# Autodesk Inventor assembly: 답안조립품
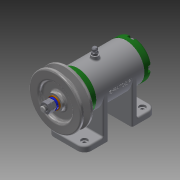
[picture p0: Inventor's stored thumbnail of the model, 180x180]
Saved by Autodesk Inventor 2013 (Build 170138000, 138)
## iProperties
Created: 2017-02
Part Number: 답안조립품
Document SubType Name: Assembly
Designer: Administrator
Author: Administrator
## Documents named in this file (16)
- C:\Users\Administrator\Desktop\470207V1029\답안조립품.iam
- C:\Users\Administrator\Desktop\470207V1029\V벨트풀리.ipt
- C:\Users\Administrator\Desktop\470207V1029\너트 M 8.ipt
- C:\Users\Administrator\Desktop\470207V1029\니플 M 6 x 0.75.ipt
- C:\Users\Administrator\Desktop\470207V1029\뒤커버.ipt
- C:\Users\Administrator\Desktop\470207V1029\베어링 15 x 32 x 9.ipt
- C:\Users\Administrator\Desktop\470207V1029\본체.ipt
- C:\Users\Administrator\Desktop\470207V1029\볼트 M 6 x 8.ipt
- C:\Users\Administrator\Desktop\470207V1029\볼트 M4 x 12.ipt
- C:\Users\Administrator\Desktop\470207V1029\스프링와셔 8.ipt
- C:\Users\Administrator\Desktop\470207V1029\앞커버.ipt
- C:\Users\Administrator\Desktop\470207V1029\오일 실 15 25 7.ipt
- C:\Users\Administrator\Desktop\470207V1029\와셔 6x11.5.ipt
- C:\Users\Administrator\Desktop\470207V1029\와셔 8x17.ipt
- C:\Users\Administrator\Desktop\470207V1029\축.ipt
- C:\Users\Administrator\Desktop\470207V1029\키 3 x 3 x 12.ipt
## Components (11 placed, 3 different names)
1. V벨트풀리:1
2. KS B 2023 6002 - 15 x 32 x 9:1
3. KS B 2023 6002 - 15 x 32 x 9:2
4. ISO 4762 M4 x 12:2
5. ISO 4762 M4 x 12:3
6. ISO 4762 M4 x 12:4
7. ISO 4762 M4 x 12:5
8. ISO 4762 M4 x 12:1
9. ISO 4762 M4 x 12:6
10. ISO 4762 M4 x 12:7
11. ISO 4762 M4 x 12:8
